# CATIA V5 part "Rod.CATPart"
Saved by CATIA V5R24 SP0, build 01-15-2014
Part number: Rod
Bounding box of the stored display mesh (mm): x -9 to 9, y -9 to 9, z -118 to 10
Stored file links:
  C:\Users\minsi\Google 드라이브\CDL_2019\00_CLASS\00_CAD\기말고사\DMU\Rod.CATPart
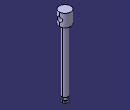
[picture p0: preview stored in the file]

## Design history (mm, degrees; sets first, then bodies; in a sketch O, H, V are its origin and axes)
Body1 (main body)
  Sketch1 on xy-plane, origin (0, 0, 0), H (1, 0, 0), V (0, 1, 0)
    circle A1 centre (0, 0) radius 9
    radius A1 = 9
  Pad1: profile Sketch1, direction (0, 0, 1), length 10, mirrored extent
  Sketch2 on yz-plane, origin (0, 6.7115, 2.9061), H (0, 1, 0), V (0, 0, 1)
    point P1 (-6.7115, -2.9061)
    reference intersected line E1 through (0, -2.9061) direction (-1, 0) from xy-plane
    reference intersected line E2 through (-6.7115, 0) direction (0, 1) from zx-plane
    coincidence: P1 E1, P1 E2
  Hole1: placed by Sketch2, at (0, 0, 0) direction (-1, 0, 0), diameter 8, through (limit type 3)
  Sketch3 on start face of Pad1, origin (0, 0, -10), H (1, 0, 0), V (0, -1, 0)
    circle A1 centre (0, 0) radius 4.5
    radius A1 = 4.5
  Pad2: profile Sketch3, direction (0, 0, -1), length 100
  Sketch4 on end face of Pad2, origin (0, 0, -110), H (1, 0, 0), V (0, -1, 0)
    circle A1 centre (0, 0) radius 3
    radius A1 = 3
  Pad3: profile Sketch4, direction (0, 0, -1), length 5
  Sketch5 on end face of Pad3, origin (0, 0, -115), H (1, 0, 0), V (0, -1, 0)
    circle A1 centre (0, 0) radius 4.5
    radius A1 = 4.5
  Pad4: profile Sketch5, direction (0, 0, -1), length 3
